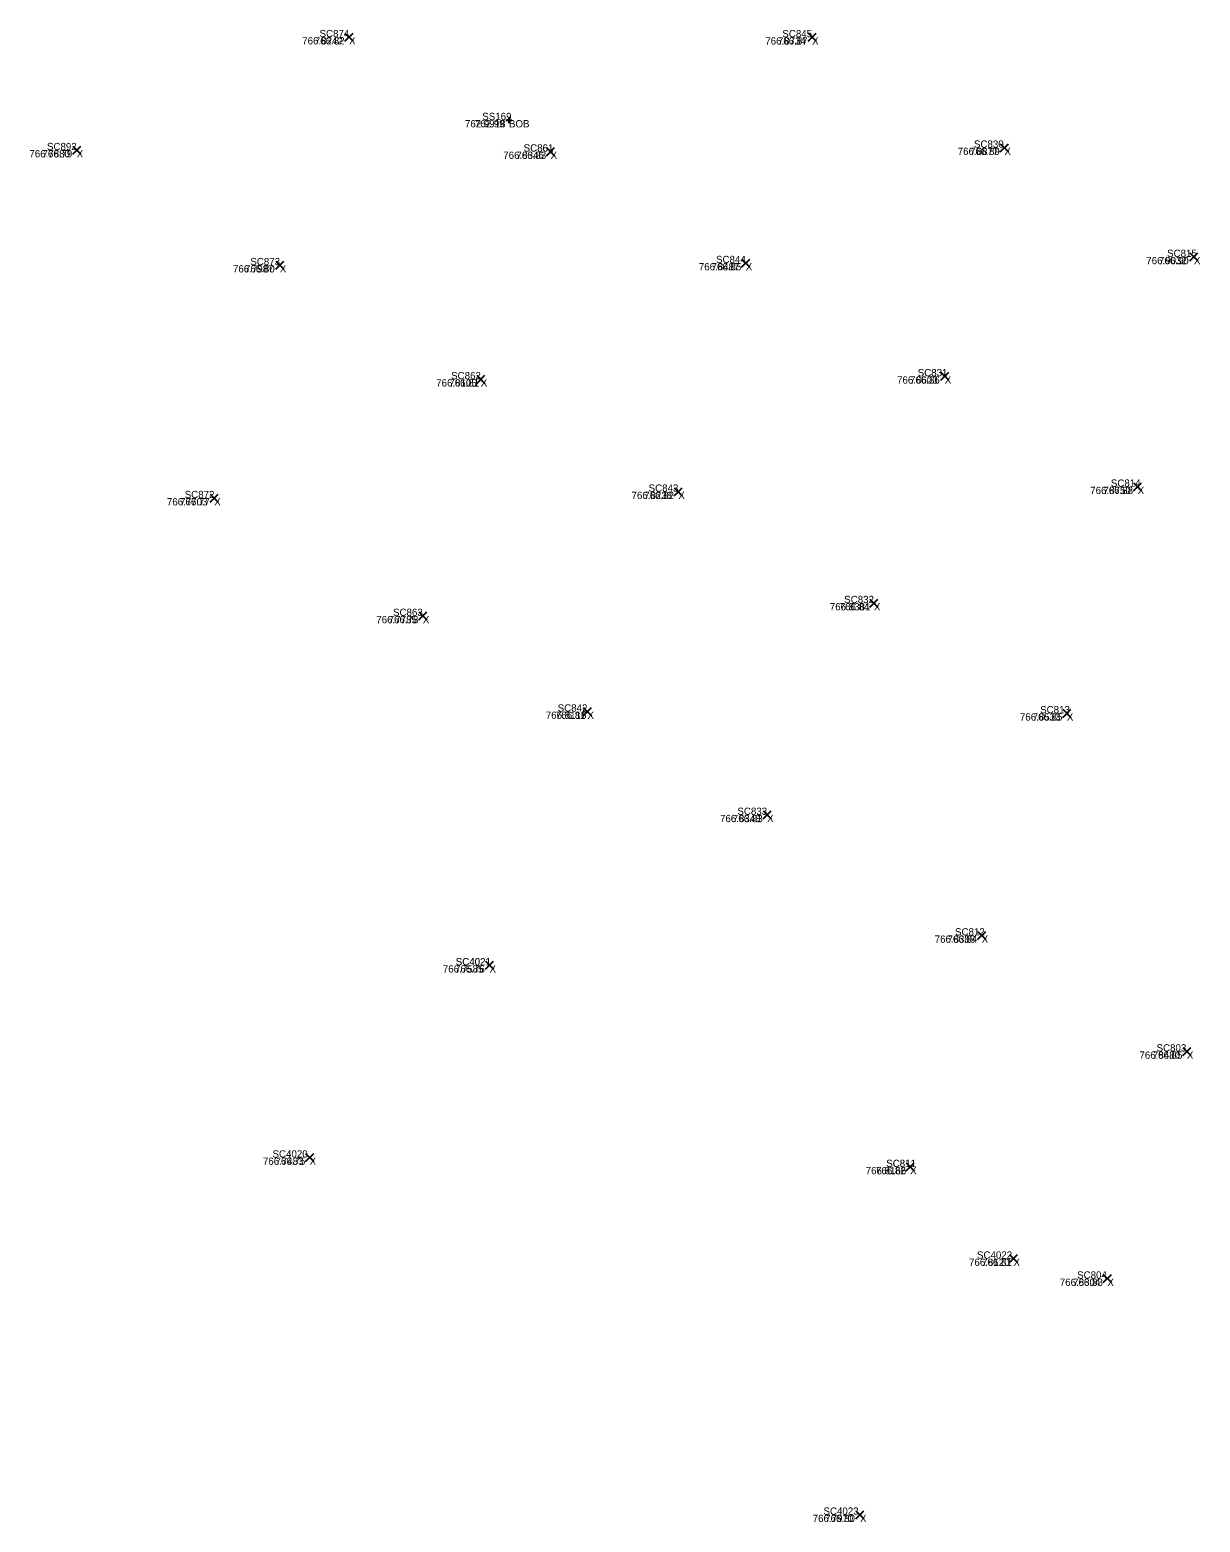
# Model space of a CAD drawing. Extents: x 1845019 to 1877956, y 680444 to 701081.
# Drawn here: x 1857592.65 to 1857602.3, y 694303.49 to 694315.8 of the extents above; entities that cross this region are included whole.
import ezdxf

# ---------------------------------------------------------------- set-up
doc = ezdxf.new("R2010")
doc.units = 0
for name, color, linetype in [('BR_X_SV_Bottom_of_Beam_Text', 7, 'Continuous'), ('SV_X_Random_Point', 7, 'Continuous'), ('SV_X_Text_Comment', 7, 'Continuous'), ('SV_X_Text_Elevation', 7, 'Continuous'), ('SV_X_Text_Name', 7, 'Continuous')]:
    doc.layers.add(name, color=color, linetype=linetype)

msp = doc.modelspace()

# ---------------------------------------------------------------- linework, layer by layer
at = {"layer": 'BR_X_SV_Bottom_of_Beam_Text'}
for p, q in [((1857596.577, 694315.054), (1857596.627, 694315.054)), ((1857596.577, 694315.054), (1857596.627, 694315.054)), ((1857596.602, 694315.079), (1857596.602, 694315.029)), ((1857596.602, 694315.079), (1857596.602, 694315.029)), ((1857596.602, 694315.054), (1857596.602, 694315.054)), ((1857596.602, 694315.054), (1857596.602, 694315.054))]:
    msp.add_line(p, q, dxfattribs=at)
at = {"layer": 'SV_X_Random_Point'}
for p, q in [((1857595.249, 694315.704), (1857595.316, 694315.771)), ((1857595.249, 694315.771), (1857595.316, 694315.704)), ((1857595.249, 694315.704), (1857595.316, 694315.771)), ((1857595.249, 694315.771), (1857595.316, 694315.704)), ((1857599.069, 694315.704), (1857599.135, 694315.77)), ((1857599.069, 694315.77), (1857599.135, 694315.704)), ((1857599.069, 694315.704), (1857599.135, 694315.77)), ((1857599.069, 694315.77), (1857599.135, 694315.704)), ((1857593.004, 694314.773), (1857593.07, 694314.84)), ((1857593.004, 694314.84), (1857593.07, 694314.773)), ((1857593.004, 694314.773), (1857593.07, 694314.84)), ((1857593.004, 694314.84), (1857593.07, 694314.773)), ((1857596.913, 694314.76), (1857596.979, 694314.827)), ((1857596.913, 694314.827), (1857596.979, 694314.76)), ((1857596.913, 694314.76), (1857596.979, 694314.827)), ((1857596.913, 694314.827), (1857596.979, 694314.76)), ((1857600.654, 694314.793), (1857600.721, 694314.859)), ((1857600.654, 694314.859), (1857600.721, 694314.793)), ((1857600.654, 694314.793), (1857600.721, 694314.859)), ((1857600.654, 694314.859), (1857600.721, 694314.793)), ((1857602.217, 694313.892), (1857602.284, 694313.958)), ((1857602.217, 694313.958), (1857602.284, 694313.892)), ((1857602.217, 694313.892), (1857602.284, 694313.958)), ((1857602.217, 694313.958), (1857602.284, 694313.892)), ((1857594.679, 694313.823), (1857594.746, 694313.89)), ((1857594.679, 694313.89), (1857594.746, 694313.823)), ((1857594.679, 694313.823), (1857594.746, 694313.89)), ((1857594.679, 694313.89), (1857594.746, 694313.823)), ((1857598.521, 694313.84), (1857598.588, 694313.907)), ((1857598.521, 694313.907), (1857598.588, 694313.84)), ((1857598.521, 694313.84), (1857598.588, 694313.907)), ((1857598.521, 694313.907), (1857598.588, 694313.84)), ((1857600.163, 694312.907), (1857600.229, 694312.973)), ((1857600.163, 694312.973), (1857600.229, 694312.907)), ((1857600.163, 694312.907), (1857600.229, 694312.973)), ((1857600.163, 694312.973), (1857600.229, 694312.907)), ((1857596.336, 694312.882), (1857596.403, 694312.949)), ((1857596.336, 694312.949), (1857596.403, 694312.882)), ((1857596.336, 694312.882), (1857596.403, 694312.949)), ((1857596.336, 694312.949), (1857596.403, 694312.882)), ((1857597.966, 694311.955), (1857598.032, 694312.021)), ((1857597.966, 694312.021), (1857598.032, 694311.955)), ((1857597.966, 694311.955), (1857598.032, 694312.021)), ((1857597.966, 694312.021), (1857598.032, 694311.955)), ((1857601.753, 694311.996), (1857601.82, 694312.062)), ((1857601.753, 694312.062), (1857601.82, 694311.996)), ((1857601.753, 694311.996), (1857601.82, 694312.062)), ((1857601.753, 694312.062), (1857601.82, 694311.996)), ((1857594.137, 694311.901), (1857594.204, 694311.968)), ((1857594.137, 694311.968), (1857594.204, 694311.901)), ((1857594.137, 694311.901), (1857594.204, 694311.968)), ((1857594.137, 694311.968), (1857594.204, 694311.901)), ((1857595.858, 694310.93), (1857595.925, 694310.996)), ((1857595.858, 694310.996), (1857595.925, 694310.93)), ((1857595.858, 694310.93), (1857595.925, 694310.996)), ((1857595.858, 694310.996), (1857595.925, 694310.93)), ((1857599.578, 694311.035), (1857599.645, 694311.102)), ((1857599.578, 694311.102), (1857599.645, 694311.035)), ((1857599.578, 694311.035), (1857599.645, 694311.102)), ((1857599.578, 694311.102), (1857599.645, 694311.035)), ((1857597.215, 694310.14), (1857597.282, 694310.207)), ((1857597.215, 694310.207), (1857597.282, 694310.14)), ((1857597.215, 694310.14), (1857597.282, 694310.207)), ((1857597.215, 694310.207), (1857597.282, 694310.14)), ((1857601.17, 694310.126), (1857601.236, 694310.193)), ((1857601.17, 694310.193), (1857601.236, 694310.126)), ((1857601.17, 694310.126), (1857601.236, 694310.193)), ((1857601.17, 694310.193), (1857601.236, 694310.126)), ((1857598.698, 694309.289), (1857598.765, 694309.355)), ((1857598.698, 694309.355), (1857598.765, 694309.289)), ((1857598.698, 694309.289), (1857598.765, 694309.355)), ((1857598.698, 694309.355), (1857598.765, 694309.289)), ((1857600.467, 694308.293), (1857600.534, 694308.36)), ((1857600.467, 694308.36), (1857600.534, 694308.293)), ((1857600.467, 694308.293), (1857600.534, 694308.36)), ((1857600.467, 694308.36), (1857600.534, 694308.293)), ((1857596.408, 694308.048), (1857596.475, 694308.115)), ((1857596.408, 694308.115), (1857596.475, 694308.048)), ((1857596.408, 694308.048), (1857596.475, 694308.115)), ((1857596.408, 694308.115), (1857596.475, 694308.048)), ((1857602.16, 694307.337), (1857602.227, 694307.404)), ((1857602.16, 694307.404), (1857602.227, 694307.337)), ((1857602.16, 694307.337), (1857602.227, 694307.404)), ((1857602.16, 694307.404), (1857602.227, 694307.337)), ((1857594.925, 694306.461), (1857594.992, 694306.528)), ((1857594.925, 694306.528), (1857594.992, 694306.461)), ((1857594.925, 694306.461), (1857594.992, 694306.528)), ((1857594.925, 694306.528), (1857594.992, 694306.461)), ((1857599.877, 694306.384), (1857599.944, 694306.45)), ((1857599.877, 694306.45), (1857599.944, 694306.384)), ((1857599.877, 694306.384), (1857599.944, 694306.45)), ((1857599.877, 694306.45), (1857599.944, 694306.384)), ((1857600.73, 694305.628), (1857600.796, 694305.695)), ((1857600.73, 694305.695), (1857600.796, 694305.628)), ((1857600.73, 694305.628), (1857600.796, 694305.695)), ((1857600.73, 694305.695), (1857600.796, 694305.628)), ((1857601.504, 694305.463), (1857601.571, 694305.529)), ((1857601.504, 694305.529), (1857601.571, 694305.463)), ((1857601.504, 694305.463), (1857601.571, 694305.529)), ((1857601.504, 694305.529), (1857601.571, 694305.463)), ((1857599.464, 694303.514), (1857599.53, 694303.581)), ((1857599.464, 694303.581), (1857599.53, 694303.514)), ((1857599.464, 694303.514), (1857599.53, 694303.581)), ((1857599.464, 694303.581), (1857599.53, 694303.514))]:
    msp.add_line(p, q, dxfattribs=at)

# ---------------------------------------------------------------- texts
at = {"layer": 'BR_X_SV_Bottom_of_Beam_Text'}
for s, p in [('762.9918', (1857596.239, 694314.994)), ('762.99', (1857596.321, 694314.994)), ('SS169', (1857596.382, 694315.054)), ('SS169', (1857596.382, 694315.054)), ('BOB', (1857596.602, 694314.994))]:
    msp.add_text(s, height=0.06, dxfattribs=at).set_placement(p)
at = {"layer": 'SV_X_Text_Comment'}
for p in [(1857595.283, 694315.678), (1857599.102, 694315.677), (1857593.037, 694314.746), (1857600.688, 694314.766), (1857596.946, 694314.734), (1857594.712, 694313.797), (1857598.555, 694313.814), (1857602.251, 694313.865), (1857596.37, 694312.856), (1857600.196, 694312.88), (1857597.999, 694311.928), (1857601.787, 694311.969), (1857594.171, 694311.875), (1857599.612, 694311.009), (1857595.892, 694310.903), (1857597.249, 694310.114), (1857601.203, 694310.1), (1857598.731, 694309.262), (1857600.501, 694308.267), (1857596.442, 694308.021), (1857602.193, 694307.31), (1857594.958, 694306.435), (1857599.911, 694306.357), (1857600.763, 694305.601), (1857601.537, 694305.436), (1857599.497, 694303.488)]:
    msp.add_text('X', height=0.06, dxfattribs=at).set_placement(p)
at = {"layer": 'SV_X_Text_Elevation'}
for s, p in [('766.8242', (1857594.897, 694315.678)), ('766.82', (1857595.001, 694315.678)), ('766.8734', (1857598.716, 694315.677)), ('766.87', (1857598.82, 694315.677)), ('766.7880', (1857592.647, 694314.746)), ('766.79', (1857592.755, 694314.746)), ('766.8877', (1857600.303, 694314.766)), ('766.89', (1857600.405, 694314.766)), ('766.8346', (1857596.555, 694314.734)), ('766.83', (1857596.664, 694314.734)), ('766.7987', (1857594.326, 694313.797)), ('766.80', (1857594.425, 694313.797)), ('766.8487', (1857598.168, 694313.814)), ('766.85', (1857598.273, 694313.814)), ('766.9032', (1857601.858, 694313.865)), ('766.90', (1857601.963, 694313.865)), ('766.8105', (1857596.002, 694312.856)), ('766.81', (1857596.11, 694312.856)), ('766.8603', (1857599.803, 694312.88)), ('766.86', (1857599.91, 694312.88)), ('766.8238', (1857597.613, 694311.928)), ('766.82', (1857597.718, 694311.928)), ('766.8750', (1857601.396, 694311.969)), ('766.88', (1857601.504, 694311.969)), ('766.7703', (1857593.781, 694311.875)), ('766.77', (1857593.89, 694311.875)), ('766.8381', (1857599.248, 694311.009)), ('766.84', (1857599.33, 694311.009)), ('766.7785', (1857595.508, 694310.903)), ('766.78', (1857595.61, 694310.903)), ('766.8116', (1857596.906, 694310.114)), ('766.81', (1857596.989, 694310.114)), ('766.8533', (1857600.816, 694310.1)), ('766.85', (1857600.921, 694310.1)), ('766.8348', (1857598.343, 694309.262)), ('766.83', (1857598.449, 694309.262)), ('766.8388', (1857600.113, 694308.267)), ('766.84', (1857600.219, 694308.267)), ('766.7585', (1857596.057, 694308.021)), ('766.76', (1857596.157, 694308.021)), ('766.8480', (1857601.802, 694307.31)), ('766.85', (1857601.911, 694307.31)), ('766.7483', (1857594.573, 694306.435)), ('766.75', (1857594.677, 694306.435)), ('766.8166', (1857599.544, 694306.357)), ('766.82', (1857599.629, 694306.357)), ('766.8120', (1857600.396, 694305.601)), ('766.81', (1857600.504, 694305.601)), ('766.8304', (1857601.145, 694305.436)), ('766.83', (1857601.255, 694305.436)), ('766.7970', (1857599.107, 694303.488)), ('766.80', (1857599.21, 694303.488))]:
    msp.add_text(s, height=0.06, dxfattribs=at).set_placement(p)
at = {"layer": 'SV_X_Text_Name'}
for s, p in [('SC874', (1857595.04, 694315.738)), ('SC874', (1857595.04, 694315.738)), ('SC845', (1857598.857, 694315.737)), ('SC845', (1857598.857, 694315.737)), ('SC892', (1857592.792, 694314.806)), ('SC892', (1857592.792, 694314.806)), ('SC861', (1857596.723, 694314.794)), ('SC861', (1857596.724, 694314.794)), ('SC830', (1857600.437, 694314.826)), ('SC830', (1857600.437, 694314.826)), ('SC815', (1857602.03, 694313.925)), ('SC815', (1857602.03, 694313.925)), ('SC873', (1857594.469, 694313.857)), ('SC873', (1857594.469, 694313.857)), ('SC844', (1857598.31, 694313.874)), ('SC844', (1857598.31, 694313.874)), ('SC862', (1857596.125, 694312.916)), ('SC862', (1857596.125, 694312.916)), ('SC831', (1857599.973, 694312.94)), ('SC831', (1857599.974, 694312.94)), ('SC872', (1857593.928, 694311.935)), ('SC872', (1857593.928, 694311.935)), ('SC843', (1857597.754, 694311.988)), ('SC843', (1857597.754, 694311.988)), ('SC814', (1857601.566, 694312.029)), ('SC814', (1857601.566, 694312.029)), ('SC832', (1857599.367, 694311.069)), ('SC832', (1857599.367, 694311.069)), ('SC863', (1857595.646, 694310.963)), ('SC863', (1857595.646, 694310.963)), ('SC842', (1857597.004, 694310.174)), ('SC842', (1857597.004, 694310.174)), ('SC813', (1857600.983, 694310.16)), ('SC813', (1857600.983, 694310.16)), ('SC833', (1857598.486, 694309.322)), ('SC833', (1857598.486, 694309.322)), ('SC812', (1857600.281, 694308.327)), ('SC812', (1857600.281, 694308.327)), ('SC4021', (1857596.163, 694308.081)), ('SC4021', (1857596.164, 694308.081)), ('SC803', (1857601.943, 694307.37)), ('SC803', (1857601.943, 694307.37)), ('SC4020', (1857594.652, 694306.495)), ('SC4020', (1857594.652, 694306.495)), ('SC811', (1857599.713, 694306.417)), ('SC811', (1857599.714, 694306.417)), ('SC4022', (1857600.462, 694305.661)), ('SC4022', (1857600.462, 694305.661)), ('SC804', (1857601.288, 694305.496)), ('SC804', (1857601.288, 694305.496)), ('SC4023', (1857599.196, 694303.548)), ('SC4023', (1857599.196, 694303.548))]:
    msp.add_text(s, height=0.06, dxfattribs=at).set_placement(p)

doc.saveas('drawing.dxf')
